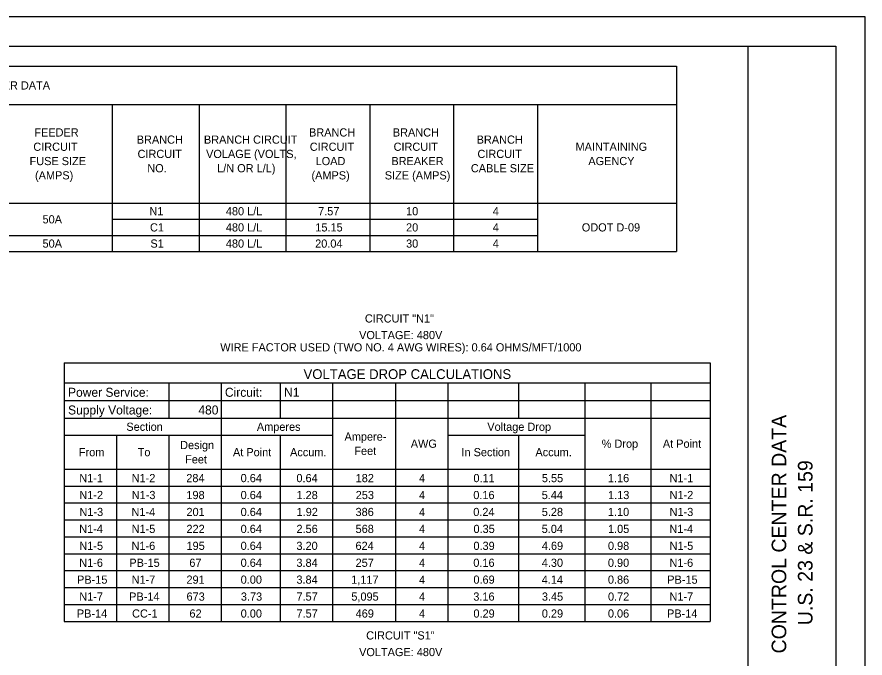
# Model space of a CAD drawing. Extents: x 0 to 34, y 0 to 22.
# Drawn here: x 19.47 to 34, y 11.02 to 22 of the extents above; entities that cross this region are included whole.
import ezdxf

# ---------------------------------------------------------------- set-up
doc = ezdxf.new("R2010")
doc.units = 0
for name, color, linetype in [('Default', 7, 'Continuous'), ('SH_Border', 7, 'Continuous'), ('SH_Cut_Line', 7, 'Continuous'), ('SH_Data', 7, 'Continuous'), ('SH_Text', 7, 'Continuous')]:
    doc.layers.add(name, color=color, linetype=linetype)

msp = doc.modelspace()

# ---------------------------------------------------------------- linework, layer by layer
at = {"layer": 'SH_Border'}
msp.add_line((32, 0.5), (32, 21.5), dxfattribs=at)
msp.add_lwpolyline([(1.5, 21.5), (33.5, 21.5), (33.5, 0.5), (1.5, 0.5)], close=True, dxfattribs=at)
at = {"layer": 'SH_Cut_Line'}
msp.add_lwpolyline([(0, 0), (34, 0), (34, 22), (0, 22)], close=True, dxfattribs=at)
at = {"layer": 'SH_Text'}
for p, q in [((6.566, 21.157), (21.1, 21.157)), ((21.1, 21.157), (30.771, 21.157)), ((30.771, 21.157), (30.771, 17.982)), ((6.566, 20.499), (21.1, 20.499)), ((21.1, 20.499), (30.771, 20.499)), ((21.1, 20.499), (21.1, 17.982)), ((22.589, 20.499), (22.589, 17.982)), ((24.078, 20.499), (24.078, 17.982)), ((25.514, 20.499), (25.514, 17.982)), ((26.95, 20.499), (26.95, 17.982)), ((28.386, 20.499), (28.386, 17.982)), ((6.566, 18.812), (21.1, 18.812)), ((21.1, 18.812), (30.771, 18.812)), ((21.1, 18.535), (28.386, 18.535)), ((16.936, 18.259), (21.1, 18.259)), ((21.1, 18.259), (28.386, 18.259)), ((6.566, 17.982), (21.1, 17.982)), ((21.1, 17.982), (30.771, 17.982)), ((20.278, 16.076), (22.966, 16.076)), ((20.278, 16.076), (20.278, 15.128)), ((22.966, 16.076), (25.957, 16.076)), ((25.957, 16.076), (26.853, 16.076)), ((26.853, 16.076), (31.346, 16.076)), ((31.346, 16.076), (31.346, 15.128)), ((20.278, 15.734), (22.966, 15.734)), ((22.07, 15.734), (22.07, 15.128)), ((22.966, 15.734), (25.957, 15.734)), ((22.966, 15.734), (22.966, 15.128)), ((23.981, 15.734), (23.981, 15.128)), ((24.877, 15.734), (24.877, 15.128)), ((25.957, 15.734), (26.853, 15.734)), ((25.957, 15.734), (25.957, 15.128)), ((26.853, 15.734), (31.346, 15.734)), ((26.853, 15.734), (26.853, 15.128)), ((28.065, 15.734), (28.065, 15.128)), ((29.198, 15.734), (29.198, 15.128)), ((30.332, 15.734), (30.332, 15.128)), ((20.278, 15.431), (22.966, 15.431)), ((22.966, 15.431), (25.957, 15.431)), ((25.957, 15.431), (26.853, 15.431)), ((26.853, 15.431), (31.346, 15.431)), ((20.278, 15.128), (22.966, 15.128)), ((20.278, 15.128), (20.278, 12.808)), ((22.966, 15.128), (25.957, 15.128)), ((22.966, 15.128), (22.966, 12.808)), ((24.877, 15.128), (24.877, 12.808)), ((25.957, 15.128), (26.853, 15.128)), ((25.957, 15.128), (25.957, 12.808)), ((26.853, 15.128), (31.346, 15.128)), ((26.853, 15.128), (26.853, 12.808)), ((29.198, 15.128), (29.198, 12.808)), ((30.332, 15.128), (30.332, 12.808)), ((31.346, 15.128), (31.346, 12.808)), ((20.278, 14.838), (22.966, 14.838)), ((21.174, 14.838), (21.174, 12.808)), ((22.07, 14.838), (22.07, 12.808)), ((22.966, 14.838), (24.877, 14.838)), ((23.981, 14.838), (23.981, 12.808)), ((26.853, 14.838), (29.198, 14.838)), ((28.065, 14.838), (28.065, 12.808)), ((20.278, 14.258), (22.966, 14.258)), ((22.966, 14.258), (25.957, 14.258)), ((25.957, 14.258), (26.853, 14.258)), ((26.853, 14.258), (31.346, 14.258)), ((20.278, 13.968), (22.966, 13.968)), ((22.966, 13.968), (25.957, 13.968)), ((25.957, 13.968), (26.853, 13.968)), ((26.853, 13.968), (31.346, 13.968)), ((20.278, 13.678), (22.966, 13.678)), ((22.966, 13.678), (25.957, 13.678)), ((25.957, 13.678), (26.853, 13.678)), ((26.853, 13.678), (31.346, 13.678)), ((20.278, 13.388), (22.966, 13.388)), ((22.966, 13.388), (25.957, 13.388)), ((25.957, 13.388), (26.853, 13.388)), ((26.853, 13.388), (31.346, 13.388)), ((20.278, 13.098), (22.966, 13.098)), ((22.966, 13.098), (25.957, 13.098)), ((25.957, 13.098), (26.853, 13.098)), ((26.853, 13.098), (31.346, 13.098)), ((20.278, 12.808), (22.966, 12.808)), ((20.278, 12.808), (20.278, 12.519)), ((21.174, 12.808), (21.174, 12.519)), ((22.07, 12.808), (22.07, 12.519)), ((22.966, 12.808), (25.957, 12.808)), ((22.966, 12.808), (22.966, 12.519)), ((23.981, 12.808), (23.981, 12.519)), ((24.877, 12.808), (24.877, 12.519)), ((25.957, 12.808), (26.853, 12.808)), ((25.957, 12.808), (25.957, 12.519)), ((26.853, 12.808), (31.346, 12.808)), ((26.853, 12.808), (26.853, 12.519)), ((28.065, 12.808), (28.065, 12.519)), ((29.198, 12.808), (29.198, 12.519)), ((30.332, 12.808), (30.332, 12.519)), ((31.346, 12.808), (31.346, 12.519)), ((20.278, 12.519), (22.966, 12.519)), ((20.278, 12.519), (20.278, 11.649)), ((21.174, 12.519), (21.174, 11.649)), ((22.07, 12.519), (22.07, 11.649)), ((22.966, 12.519), (25.957, 12.519)), ((22.966, 12.519), (22.966, 11.649)), ((23.981, 12.519), (23.981, 11.649)), ((24.877, 12.519), (24.877, 11.649)), ((25.957, 12.519), (26.853, 12.519)), ((25.957, 12.519), (25.957, 11.649)), ((26.853, 12.519), (31.346, 12.519)), ((26.853, 12.519), (26.853, 11.649)), ((28.065, 12.519), (28.065, 11.649)), ((29.198, 12.519), (29.198, 11.649)), ((30.332, 12.519), (30.332, 11.649)), ((31.346, 12.519), (31.346, 11.649)), ((20.278, 12.229), (22.966, 12.229)), ((22.966, 12.229), (25.957, 12.229)), ((25.957, 12.229), (26.853, 12.229)), ((26.853, 12.229), (31.346, 12.229)), ((20.278, 11.939), (22.966, 11.939)), ((22.966, 11.939), (25.957, 11.939)), ((25.957, 11.939), (26.853, 11.939)), ((26.853, 11.939), (31.346, 11.939)), ((20.278, 11.649), (22.966, 11.649)), ((22.966, 11.649), (25.957, 11.649)), ((25.957, 11.649), (26.853, 11.649)), ((26.853, 11.649), (31.346, 11.649))]:
    msp.add_line(p, q, dxfattribs=at)

# ---------------------------------------------------------------- texts
at = {"layer": 'Default'}
for s, p in [('CIRCUIT "N1"', (25.43, 16.768)), ('VOLTAGE: 480V ', (25.331, 16.483)), ('WIRE FACTOR USED (TWO NO. 4 AWG WIRES): 0.64 OHMS/MFT/1000', (22.952, 16.273)), ('CIRCUIT "S1"', (25.452, 11.34)), ('VOLTAGE: 480V ', (25.331, 11.055))]:
    msp.add_text(s, height=0.14, dxfattribs=at).set_placement(p)
at = {"layer": 'SH_Data'}
for s, p in [('CONTROL CENTER DATA', (32.65, 11.101)), ('U.S. 23 & S.R. 159', (33.1, 11.585))]:
    msp.add_text(s, height=0.25, rotation=90, dxfattribs=at).set_placement(p)
at = {"layer": 'SH_Text'}
for s, height, p in [('CONTROL CENTER DATA', 0.14, (17.747, 20.758)), ('FEEDER ', 0.14, (19.766, 19.953)), ('BRANCH ', 0.14, (24.473, 19.953)), ('BRANCH ', 0.14, (25.909, 19.953)), ('BRANCH ', 0.14, (21.521, 19.83)), ('BRANCH CIRCUIT ', 0.14, (22.672, 19.83)), ('BRANCH ', 0.14, (27.345, 19.83)), ('CIRCUIT ', 0.14, (19.749, 19.708)), ('CIRCUIT ', 0.14, (24.486, 19.708)), ('CIRCUIT ', 0.14, (25.922, 19.708)), ('MAINTAINING', 0.14, (29.04, 19.708)), ('CIRCUIT ', 0.14, (21.535, 19.585)), ('VOLAGE (VOLTS, ', 0.14, (22.709, 19.585)), ('CIRCUIT ', 0.14, (27.359, 19.585)), ('FUSE SIZE ', 0.14, (19.685, 19.463)), ('NO.', 0.14, (21.702, 19.34)), ('L/N OR L/L)', 0.14, (22.899, 19.34)), ('LOAD ', 0.14, (24.586, 19.463)), ('BREAKER ', 0.14, (25.884, 19.463)), ('CABLE SIZE', 0.14, (27.246, 19.34)), ('AGENCY', 0.14, (29.259, 19.463)), ('(AMPS)', 0.14, (19.778, 19.218)), ('(AMPS)', 0.14, (24.515, 19.218)), ('SIZE (AMPS)', 0.14, (25.771, 19.218)), ('480 L/L', 0.14, (23.048, 18.604)), ('10', 0.14, (26.136, 18.604)), ('50A', 0.14, (19.907, 18.465)), ('N1', 0.14, (21.738, 18.604)), ('7.57', 0.14, (24.629, 18.604)), ('4', 0.14, (27.621, 18.604)), ('C1', 0.14, (21.748, 18.327)), ('480 L/L', 0.14, (23.048, 18.327)), ('15.15', 0.14, (24.581, 18.327)), ('20', 0.14, (26.136, 18.327)), ('4', 0.14, (27.621, 18.327)), ('ODOT D-09', 0.14, (29.147, 18.327)), ('50A', 0.14, (19.907, 18.05)), ('S1', 0.14, (21.755, 18.05)), ('480 L/L', 0.14, (23.048, 18.05)), ('20.04', 0.14, (24.578, 18.05)), ('30', 0.14, (26.136, 18.05)), ('4', 0.14, (27.621, 18.05)), ('VOLTAGE DROP CALCULATIONS', 0.168, (24.379, 15.8)), ('Power Service:', 0.154, (20.344, 15.496)), ('Circuit:', 0.154, (23.032, 15.496)), ('N1', 0.154, (24.046, 15.496)), ('Supply Voltage:', 0.154, (20.344, 15.193)), ('480', 0.154, (22.577, 15.193)), ('Section', 0.14, (21.343, 14.913)), ('Amperes', 0.14, (23.579, 14.913)), ('Voltage Drop', 0.14, (27.528, 14.913)), ('Ampere-', 0.14, (25.081, 14.745)), ('Design', 0.14, (22.264, 14.6)), ('AWG', 0.14, (26.216, 14.623)), ('% Drop', 0.14, (29.488, 14.623)), ('At Point', 0.14, (30.536, 14.623)), ('From', 0.14, (20.53, 14.478)), ('To', 0.14, (21.537, 14.478)), ('At Point', 0.14, (23.17, 14.478)), ('Accum.', 0.14, (24.148, 14.478)), ('Feet', 0.14, (25.249, 14.5)), ('In Section', 0.14, (27.085, 14.478)), ('Accum.', 0.14, (28.352, 14.478)), ('Feet', 0.14, (22.35, 14.355)), ('N1-1', 0.14, (20.537, 14.034)), ('N1-2', 0.14, (21.434, 14.034)), ('284', 0.14, (22.37, 14.034)), ('0.64', 0.14, (23.301, 14.034)), ('0.64', 0.14, (24.257, 14.034)), ('182', 0.14, (25.272, 14.034)), ('4', 0.14, (26.358, 14.034)), ('0.11', 0.14, (27.29, 14.034)), ('5.55', 0.14, (28.463, 14.034)), ('1.16', 0.14, (29.594, 14.034)), ('N1-1', 0.14, (30.65, 14.034)), ('N1-2', 0.14, (20.538, 13.744)), ('N1-3', 0.14, (21.435, 13.744)), ('198', 0.14, (22.372, 13.744)), ('0.64', 0.14, (23.301, 13.744)), ('1.28', 0.14, (24.258, 13.744)), ('253', 0.14, (25.273, 13.744)), ('4', 0.14, (26.358, 13.744)), ('0.16', 0.14, (27.288, 13.744)), ('5.44', 0.14, (28.46, 13.744)), ('1.13', 0.14, (29.597, 13.744)), ('N1-2', 0.14, (30.651, 13.744)), ('N1-3', 0.14, (20.539, 13.454)), ('N1-4', 0.14, (21.431, 13.454)), ('201', 0.14, (22.373, 13.454)), ('0.64', 0.14, (23.301, 13.454)), ('1.92', 0.14, (24.26, 13.454)), ('386', 0.14, (25.27, 13.454)), ('4', 0.14, (26.358, 13.454)), ('0.24', 0.14, (27.287, 13.454)), ('5.28', 0.14, (28.461, 13.454)), ('1.10', 0.14, (29.594, 13.454)), ('N1-3', 0.14, (30.651, 13.454)), ('N1-4', 0.14, (20.535, 13.164)), ('N1-5', 0.14, (21.434, 13.164)), ('222', 0.14, (22.373, 13.164)), ('0.64', 0.14, (23.301, 13.164)), ('2.56', 0.14, (24.258, 13.164)), ('568', 0.14, (25.271, 13.164)), ('4', 0.14, (26.358, 13.164)), ('0.35', 0.14, (27.291, 13.164)), ('5.04', 0.14, (28.46, 13.164)), ('1.05', 0.14, (29.596, 13.164)), ('N1-4', 0.14, (30.648, 13.164)), ('N1-5', 0.14, (20.538, 12.874)), ('N1-6', 0.14, (21.432, 12.874)), ('195', 0.14, (22.374, 12.874)), ('0.64', 0.14, (23.301, 12.874)), ('3.20', 0.14, (24.257, 12.874)), ('624', 0.14, (25.269, 12.874)), ('4', 0.14, (26.358, 12.874)), ('0.39', 0.14, (27.29, 12.874)), ('4.69', 0.14, (28.462, 12.874)), ('0.98', 0.14, (29.595, 12.874)), ('N1-5', 0.14, (30.651, 12.874)), ('N1-6', 0.14, (20.536, 12.584)), ('PB-15', 0.14, (21.394, 12.584)), ('67', 0.14, (22.422, 12.584)), ('0.64', 0.14, (23.301, 12.584)), ('3.84', 0.14, (24.257, 12.584)), ('257', 0.14, (25.271, 12.584)), ('4', 0.14, (26.358, 12.584)), ('0.16', 0.14, (27.288, 12.584)), ('4.30', 0.14, (28.461, 12.584)), ('0.90', 0.14, (29.594, 12.584)), ('N1-6', 0.14, (30.649, 12.584)), ('PB-15', 0.14, (20.498, 12.295)), ('N1-7', 0.14, (21.433, 12.295)), ('291', 0.14, (22.373, 12.295)), ('0.00', 0.14, (23.302, 12.295)), ('3.84', 0.14, (24.257, 12.295)), ('1,117', 0.14, (25.196, 12.295)), ('4', 0.14, (26.358, 12.295)), ('0.69', 0.14, (27.29, 12.295)), ('4.14', 0.14, (28.46, 12.295)), ('0.86', 0.14, (29.594, 12.295)), ('PB-15', 0.14, (30.611, 12.295)), ('N1-7', 0.14, (20.537, 12.005)), ('PB-14', 0.14, (21.391, 12.005)), ('673', 0.14, (22.374, 12.005)), ('3.73', 0.14, (23.305, 12.005)), ('7.57', 0.14, (24.258, 12.005)), ('5,095', 0.14, (25.198, 12.005)), ('4', 0.14, (26.358, 12.005)), ('3.16', 0.14, (27.288, 12.005)), ('3.45', 0.14, (28.463, 12.005)), ('0.72', 0.14, (29.596, 12.005)), ('N1-7', 0.14, (30.649, 12.005)), ('PB-14', 0.14, (20.495, 11.715)), ('CC-1', 0.14, (21.441, 11.715)), ('62', 0.14, (22.424, 11.715)), ('0.00', 0.14, (23.302, 11.715)), ('7.57', 0.14, (24.258, 11.715)), ('469', 0.14, (25.272, 11.715)), ('4', 0.14, (26.358, 11.715)), ('0.29', 0.14, (27.29, 11.715)), ('0.29', 0.14, (28.462, 11.715)), ('0.06', 0.14, (29.594, 11.715)), ('PB-14', 0.14, (30.608, 11.715))]:
    msp.add_text(s, height=height, dxfattribs=at).set_placement(p)

doc.saveas('drawing.dxf')
